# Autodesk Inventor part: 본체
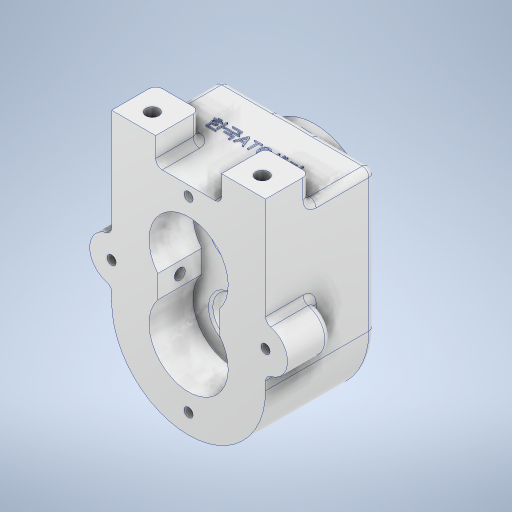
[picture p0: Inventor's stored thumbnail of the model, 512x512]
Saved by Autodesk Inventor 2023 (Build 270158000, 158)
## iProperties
Created: 2024-03
Part Number: 본체
Material: 알루미늄 6061
Document SubType Name: Modeling
Designer: asung
Density: 2.7 g/cm^3
Appearance: 알루미늄 - 평지
Author: asung
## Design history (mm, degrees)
sketch "스케치1"
  geometry: L1 (-35, 0)-(-35, 63.5); L2 (35, 0)-(35, 63.5); L3 (-35, 63.5)-(35, 63.5); A1 r 35 centre (0, 0) between (-35, 0) and (35, 0); 3 further points
  constraints: 6 end point, 2 point on circle, 2 tangent, 2 vertical, 1 centre point, 1 coincident, 1 horizontal
  dimensions: "d0" = 70 diameter of A1; "d2" = 70 distance of L3.start L3.end; "d3" = 63.5 distance from line of point (0, 0) L3; "d4" = 0 distance from line of L2.end L3; "d5" = 0 distance from line of L3.end L2; "d6" = 0 distance from line of L1.end L3
extrude "돌출1" new body sketch "스케치1" distance "d7" = 50; taper "d8" = 0 deg
sketch "스케치2"
  geometry: L1 (-35, 0)-(-35, 63.5) reference; L2 (-35, 63.5)-(35, 63.5) reference; L3 (35, 63.5)-(35, 0) reference; L4 (0, 0)-(0, 33); L5 (14, 11.314)-(14, 21.686); L6 (-14, 11.314)-(-14, 21.686); L7 (-35, 0)-(-35, 63.5) reference; L8 (-35, 63.5)-(35, 63.5) reference; L9 (35, 63.5)-(35, 0) reference; A1 r 35 centre (0, 0) between (-35, 0) and (35, 0) reference; A2 r 18 centre (0, 0) between (-14, 11.314) and (14, 11.314); A3 r 18 centre (0, 33) between (14, 21.686) and (-14, 21.686); A4 r 35 centre (0, 0) between (-35, 0) and (35, 0) reference; 1 further point
  constraints: 6 end point, 4 point on circle, 2 centre point, 2 coincident, 2 parallel, 1 vertical
  dimensions: "d9" = 36 diameter of A2; "d10" = 33 distance of L4.start L4.end; "d11" = 36 diameter of A3; "d13" = 14 distance between parallel lines of L4 L6
extrude "돌출2" cut sketch "스케치2" distance "d14" = 20; taper "d15" = 0 deg
sketch "스케치4"
  geometry: L1 (-14, 21.686)-(-14, 11.314) reference; L2 (14, 11.314)-(14, 21.686) reference; L3 (-35, 0)-(-35, 63.5) reference; L4 (-35, 63.5)-(35, 63.5) reference; L5 (35, 63.5)-(35, 0) reference; L6 (-35, 63.5)-(-15, 63.5); L7 (-15, 63.5)-(-15, 75.5); L8 (-15, 75.5)-(-35, 75.5); L9 (-35, 75.5)-(-35, 63.5); L10 (35, 63.5)-(15, 63.5); L11 (15, 63.5)-(15, 75.5); L12 (15, 75.5)-(35, 75.5); L13 (35, 75.5)-(35, 63.5); A1 r 18 centre (0, 33) between (14, 21.686) and (-14, 21.686) reference; A2 r 18 centre (0, 0) between (-14, 11.314) and (14, 11.314) reference; A3 r 35 centre (0, 0) between (-35, 0) and (35, 0) reference; 5 further points
  constraints: 16 end point, 4 parallel, 2 horizontal, 2 midpoint, 2 perpendicular
  dimensions: "d16" = 30 distance of L11.end L7.end; "d20" = 20 distance of L7.end L8.end; "d21" = 20 distance of L12.end L11.end; "d22" = 12 distance between parallel lines of L4 L12
extrude "돌출3" join sketch "스케치4" distance "d23" = 20; taper "d24" = 0 deg
fillet "모깎기1" dims "d25" = 3
fillet "모깎기2" dims "d26" = 3
fillet "모깎기3" dims "d27" = 3
sketch "스케치5"
  geometry: L1 (-35, 0)-(-35, 75.5) reference; L2 (-35, 75.5)-(-15, 75.5) reference; L3 (-15, 75.5)-(-15, 66.5) reference; L4 (-12, 63.5)-(12, 63.5) reference; L5 (15, 66.5)-(15, 75.5) reference; L6 (15, 75.5)-(35, 75.5) reference; L7 (35, 75.5)-(35, 0) reference; L8 (-14, 21.686)-(-14, 11.314) reference; L9 (14, 11.314)-(14, 21.686) reference; L10 (0, 0)-(0, -26); L11 (-14, 16.5)-(14, 16.5); L12 (0, 33)-(0, 0); L13 (-35, 33)-(-35, 0); L14 (35, 33)-(35, 0); A1 r 3 centre (-12, 66.5) between (-15, 66.5) and (-12, 63.5) reference; A2 r 3 centre (12, 66.5) between (12, 63.5) and (15, 66.5) reference; A3 r 35 centre (0, 0) between (-35, 0) and (35, 0) reference; A4 r 18 centre (0, 33) between (14, 21.686) and (-14, 21.686) reference; A5 r 18 centre (0, 0) between (-14, 11.314) and (14, 11.314) reference; A6 r 10 centre (-35, 16.5) between (-35, 26.5) and (-35, 6.5); A7 r 10 centre (35, 16.5) between (35, 6.5) and (35, 26.5); 7 further points
  constraints: 10 end point, 6 midpoint, 4 point on circle, 4 point on line, 2 centre point, 2 horizontal alignment, 2 parallel, 2 vertical
  dimensions: "d28" = 26 distance of L10.start L10.end; "d29" = 35 distance between parallel lines of L12 L13; "d30" = 35 distance between parallel lines of L12 L14; "d31" = 10 radius of A6; "d32" = 10 radius of A7
extrude "돌출4" join sketch "스케치5" distance "d33" = 20; taper "d34" = 0 deg
fillet "모깎기4" dims "d35" = 3
fillet "모깎기5" dims "d36" = 3
sketch "스케치6"
  geometry: A1 r 10 centre (35, 16.5) between (37.308, 6.77) and (37.308, 26.23) reference; A2 r 10 centre (-35, 16.5) between (-37.308, 26.23) and (-37.308, 6.77) reference; 3 further points
  constraints: 2 coincident
hole "구멍1" sketch "스케치6" at (35, 16.5), (-35, 16.5) diameter "d37" = 4.134; stored, may be unused: countersink angle "d41" = 90 deg, drill point angle "d43" = 118 deg; dims "d38" = 10, "d39" = 7, "d40" = 3, "d42" = 12
sketch "스케치8"
  geometry: L1 (14, 21.686)-(14, 11.314) reference; L2 (-14, 11.314)-(-14, 21.686) reference; L3 (35, 0)-(35, 3.851) reference; L4 (35, 29.149)-(35, 75.5) reference; L5 (35, 75.5)-(15, 75.5) reference; L6 (15, 75.5)-(15, 66.5) reference; L7 (12, 63.5)-(-12, 63.5) reference; L8 (-15, 66.5)-(-15, 75.5) reference; L9 (-15, 75.5)-(-35, 75.5) reference; L10 (-35, 75.5)-(-35, 29.149) reference; L11 (-35, 3.851)-(-35, 0) reference; L12 (0, 0)-(0, -26); L13 (0, 33)-(0, 59); C1 r 2.067 at (35, 16.5) reference; C2 r 2.067 at (-35, 16.5) reference; A1 r 18 centre (0, 33) between (14, 21.686) and (-14, 21.686) reference; A2 r 18 centre (0, 0) between (-14, 11.314) and (14, 11.314) reference; A3 r 35 centre (0, 0) between (-35, 0) and (35, 0) reference; A4 r 3 centre (38, 3.851) between (37.308, 6.77) and (35, 3.851) reference; A5 r 10 centre (35, 16.5) between (37.308, 6.77) and (37.308, 26.23) reference; A6 r 3 centre (38, 29.149) between (35, 29.149) and (37.308, 26.23) reference; A7 r 3 centre (12, 66.5) between (12, 63.5) and (15, 66.5) reference; A8 r 3 centre (-12, 66.5) between (-15, 66.5) and (-12, 63.5) reference; A9 r 3 centre (-38, 29.149) between (-37.308, 26.23) and (-35, 29.149) reference; A10 r 10 centre (-35, 16.5) between (-37.308, 26.23) and (-37.308, 6.77) reference; A11 r 3 centre (-38, 3.851) between (-35, 3.851) and (-37.308, 6.77) reference; 1 further point
  constraints: 4 end point, 2 vertical
  dimensions: "d44" = 26 distance of L12.start L12.end; "d45" = 26 distance of L13.start L13.end
hole "구멍2" sketch "스케치8" at (0, -26), (0, 59) diameter "d46" = 4.134; stored, may be unused: countersink angle "d50" = 90 deg, drill point angle "d52" = 118 deg; dims "d47" = 10, "d48" = 4, "d49" = 2, "d51" = 12
sketch "스케치12"
  geometry: L1 (50, -43.392)-(0, -43.392) reference; L2 (0, -43.392)-(0, -22.627) reference; L3 (0, -22.627)-(20, -22.627) reference; L4 (20, -22.627)-(20, 0) reference; L5 (20, 0)-(0, 0) reference; L6 (0, 0)-(0, 10.373) reference; L7 (0, 10.373)-(20, 10.373) reference; L8 (20, 10.373)-(20, 33) reference; L9 (20, 33)-(0, 33) reference; L10 (0, 33)-(0, 52.95) reference; L11 (0, 52.95)-(17, 52.95) reference; L12 (21.472, 52.186)-(50, 52.186) reference; L13 (50, 52.186)-(50, -43.392) reference; L14 (20, 0)-(20, 10.373) reference; C1 r 2.5 at (10, 5.186); 2 further points
  constraints: 1 centre point, 1 horizontal alignment, 1 midpoint, 1 other
  dimensions: "d53" = 5 diameter of C1; "d54" = 10 distance of C1.centre point (0, 5.186)
extrude "돌출5" cut sketch "스케치12" distance "d55" = 10; taper "d56" = 0 deg
sketch "스케치15"
  geometry: L1 (-35, 63.5)-(35, 63.5) reference; L2 (35, 63.5)-(35, 0) reference; L3 (-35, 0)-(-35, 63.5) reference; L4 (0, 0)-(0, 33); C1 r 26 at (0, 33); A1 r 35 centre (0, 0) between (-35, 0) and (35, 0) reference; 1 further point
  constraints: 2 end point, 1 centre point, 1 coincident, 1 vertical
  dimensions: "d57" = 33 distance of L4.start L4.end; "d58" = 52 diameter of C1
extrude "돌출6" join sketch "스케치15" distance "d60" = 7.3; taper "d61" = 0 deg
sketch "스케치17"
  geometry: C1 r 26 at (0, 0) reference; C2 r 16 at (0, 0); 1 further point
  constraints: 1 centre point, 1 coincident
  dimensions: "d62" = 32 diameter of C2
extrude "돌출7" join sketch "스케치17" distance "d63" = 4; taper "d64" = 0 deg
fillet "모깎기6" dims "d65" = 3
sketch "스케치21"
  geometry: L1 (14, 21.686)-(14, 11.314) reference; L2 (-14, 11.314)-(-14, 21.686) reference; L3 (35, 0)-(35, 3.851) reference; L4 (35, 29.149)-(35, 75.5) reference; L5 (35, 75.5)-(15, 75.5) reference; L6 (15, 75.5)-(15, 66.5) reference; L7 (12, 63.5)-(-12, 63.5) reference; L8 (-15, 66.5)-(-15, 75.5) reference; L9 (-15, 75.5)-(-35, 75.5) reference; L10 (-35, 75.5)-(-35, 29.149) reference; L11 (-35, 3.851)-(-35, 0) reference; C1 r 2.067 at (0, -26) reference; C2 r 2.067 at (0, 59) reference; C3 r 2.067 at (35, 16.5) reference; C4 r 2.067 at (-35, 16.5) reference; C5 r 10 at (0, 33); C6 r 10 at (0, 0); A1 r 18 centre (0, 33) between (14, 21.686) and (-14, 21.686) reference; A2 r 18 centre (0, 0) between (-14, 11.314) and (14, 11.314) reference; A3 r 35 centre (0, 0) between (-35, 0) and (35, 0) reference; A4 r 3 centre (38, 3.851) between (37.308, 6.77) and (35, 3.851) reference; A5 r 10 centre (35, 16.5) between (37.308, 6.77) and (37.308, 26.23) reference; A6 r 3 centre (38, 29.149) between (35, 29.149) and (37.308, 26.23) reference; A7 r 3 centre (12, 66.5) between (12, 63.5) and (15, 66.5) reference; A8 r 3 centre (-12, 66.5) between (-15, 66.5) and (-12, 63.5) reference; A9 r 3 centre (-38, 29.149) between (-37.308, 26.23) and (-35, 29.149) reference; A10 r 10 centre (-35, 16.5) between (-37.308, 26.23) and (-37.308, 6.77) reference; A11 r 3 centre (-38, 3.851) between (-35, 3.851) and (-37.308, 6.77) reference; 1 further point
  constraints: 2 centre point, 2 coincident
  dimensions: "d91" = 20 diameter of C5; "d92" = 20 diameter of C6
extrude "돌출8" cut sketch "스케치21" distance "d93" = 10; taper "d94" = 0 deg
sketch "스케치22"
  geometry: L1 (-18, 50)-(-18, 30) reference; L2 (-18, 30)-(-10, 30) reference; L3 (-10, 30)-(-10, 20) reference; L4 (-10, 20)-(10, 20) reference; L5 (10, 20)-(10, 30) reference; L6 (10, 30)-(23, 30) reference; L7 (23, 30)-(23, 20) reference; L8 (43, 20)-(43, 30) reference; L9 (43, 30)-(51, 30) reference; L10 (51, 30)-(51, 50) reference; L11 (51, 50)-(56.933, 50) reference; L12 (56.933, 50)-(56.933, 38) reference; L13 (56.933, 38)-(59, 36.758) reference; L14 (59, 36.758)-(61.067, 38) reference; L15 (61.067, 38)-(61.067, 50) reference; L16 (61.067, 50)-(63.5, 50) reference; L17 (63.5, 50)-(63.5, 0) reference; L18 (63.5, 0)-(62, 0) reference; L19 (59, -3)-(59, -7.3) reference; L20 (59, -7.3)-(49, -7.3) reference; L21 (49, -7.3)-(49, -11.3) reference; L22 (49, -11.3)-(17, -11.3) reference; L23 (17, -11.3)-(17, -7.3) reference; L24 (17, -7.3)-(7, -7.3) reference; L25 (7, -7.3)-(7, -3) reference; L26 (4, 0)-(-35, 0) reference; L27 (-35, 0)-(-35, 50) reference; L28 (-35, 50)-(-28.067, 50) reference; L29 (-28.067, 50)-(-28.067, 38) reference; L30 (-28.067, 38)-(-26, 36.758) reference; L31 (-26, 36.758)-(-23.933, 38) reference; L32 (-23.933, 38)-(-23.933, 50) reference; L33 (-23.933, 50)-(-18, 50) reference; L34 (-10, 30)-(10, 30) reference; L35 (0, 30)-(0, 15.959); L36 (23, 20)-(43, 20) reference; L37 (7, 30)-(7, 20); L38 (0, 15.959)-(7, 20); L39 (7, 20)-(0, 20); A1 r 3 centre (62, -3) between (62, 0) and (59, -3) reference; A2 r 3 centre (4, -3) between (7, -3) and (4, 0) reference; 3 further points
  constraints: 8 end point, 2 midpoint, 2 point on line, 1 parallel, 1 vertical
  dimensions: "d143" = 7 distance between parallel lines of L35 L37; "d144" = 60 deg angle of L35 L38
  node "절단 모서리 투영9"
chamfer "모따기1" distance "d97" = 1; stored, may be unused: second distance "d98" = 2, angle "d99" = 45 deg
chamfer "모따기2" distance "d100" = 1; stored, may be unused: second distance "d101" = 2, angle "d102" = 45 deg
sketch "스케치24"
  geometry: C1 r 16 at (0, 0) reference; 2 further points
  constraints: 1 coincident
hole "구멍6" sketch "스케치24" at (0, 0) diameter "d103" = 15; stored, may be unused: countersink angle "d107" = 90 deg, drill point angle "d109" = 0 deg; dims "d104" = 8, "d105" = 25, "d106" = 7.3, "d108" = 31.5
chamfer "모따기3" distance "d110" = 1; stored, may be unused: second distance "d111" = 2, angle "d112" = 45 deg
fillet "모깎기7" dims "d113" = 3
fillet "모깎기8" dims "d114" = 3
sketch "스케치25" dims "d115" = 42
  geometry: C1 r 16 at (0, 0) reference; C2 r 26 at (0, 0) reference; 3 further points
  constraints: 1 coincident, 1 vertical alignment, 2 other
hole "구멍7" sketch "스케치25" at (0, 21) diameter "d116" = 3.242; stored, may be unused: countersink angle "d120" = 90 deg, drill point angle "d122" = 118 deg; dims "d117" = 8, "d118" = 25, "d119" = 7.3, "d121" = 10
sketch "스케치26"
  geometry: 1 further point
sketch "스케치27"
  geometry: 1 further point
sketch "스케치28"
  geometry: L1 (20, 17)-(20, 0) reference; L2 (20, 0)-(0, 0) reference; L3 (0, 0)-(0, 17) reference; L4 (3, 20)-(17, 20) reference; L5 (53, 20)-(67, 20) reference; L6 (70, 17)-(70, 0) reference; L7 (70, 0)-(50, 0) reference; L8 (50, 0)-(50, 17) reference; L9 (35, 50)-(35, 41.357); C1 r 3 at (10, 8.5); C2 r 3 at (60, 8.5); A1 r 3 centre (3, 17) between (3, 20) and (0, 17) reference; A2 r 3 centre (17, 17) between (20, 17) and (17, 20) reference; A3 r 3 centre (53, 17) between (53, 20) and (50, 17) reference; A4 r 3 centre (67, 17) between (70, 17) and (67, 20) reference; 1 further point
  constraints: 2 centre point, 2 end point, 1 midpoint, 1 symmetric about line, 1 vertical, 1 vertical alignment, 1 other
  dimensions: "d126" = 6 diameter of C1; "d127" = 8.5 distance from line of C1.centre L2
extrude "돌출9" cut sketch "스케치28" distance "d128" = 16; taper "d129" = 0 deg
sketch "스케치29"
  geometry: L1 (24, 0)-(0, 0) reference; 3 further points
  constraints: 1 midpoint, 1 other
  dimensions: "d130" = 30 vertical distance of point (12, 0) point (11.867, 30)
feature "엠보싱1" sketch "스케치29" dims "d0" = 70, "d2" = 70, "d3" = 63.5, "d4" = 0, "d5" = 0, "d6" = 0, "d131" = 0.5, "d132" = 0
chamfer "모따기4" distance "d134" = 1; stored, may be unused: second distance "d135" = 2, angle "d136" = 45 deg
revolve "회전3" stored, may be unused: angle "d145" = 90 deg
node "솔리드1"
mirror "미러1"
pattern_circular "원형 패턴2" dims angle "d124" = 360 deg
node "투영된 루프2"
node "투영된 루프4"
node "투영된 루프7"
node "투영된 루프9"
node "절단 모서리 투영1"
node "절단 모서리 투영3"
node "절단 모서리 투영4"
node "절단 모서리 투영5"
node "절단 모서리 투영8"
node "절단 모서리 투영10"
node "절단 모서리 투영11"
feature "A9D066F2-1C7D-4E18-AEED-F7BC21143FA4" dims "d46" = 4.134, "d47" = 10, "d48" = 4, "d49" = 2, "d50" = 90 deg, "d51" = 12, "d52" = 118 deg
